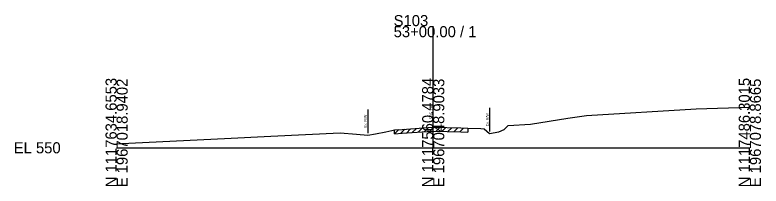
# Model space of a CAD drawing. Extents: x -26 to 163, y -10 to 24018.
# Drawn here: x -25.7 to 162.8, y 2490.3 to 2533.6 of the extents above; entities that cross this region are included whole.
import ezdxf

# ---------------------------------------------------------------- set-up
doc = ezdxf.new("R2010")
doc.units = 0
for name, color, linetype in [('RD_GPK_XS_Cell', 7, 'Continuous'), ('RD_XS_ExGround', 7, 'Continuous'), ('RD_XS_ExPaveRet', 7, 'Continuous'), ('RD_XS_ExRW', 7, 'Continuous'), ('RD_XS_TX_Elev_EX', 7, 'Continuous')]:
    doc.layers.add(name, color=color, linetype=linetype)

msp = doc.modelspace()

# ---------------------------------------------------------------- linework, layer by layer
at = {"layer": 'RD_GPK_XS_Cell'}
for p, q in [((80, 2500), (80, 2530.77)), ((0, 2500), (80, 2500)), ((80, 2500), (160, 2500))]:
    msp.add_line(p, q, dxfattribs=at)
at = {"layer": 'RD_XS_ExGround'}
msp.add_lwpolyline([(0, 2501.04), (1.35, 2501.12), (27.23, 2502.39), (38.97, 2502.95), (56.49, 2503.78), (60.59, 2503.44), (63.45, 2503.22), (65.42, 2503.56), (68.03, 2504.01), (69.5, 2504.37), (70.21, 2504.5), (72.18, 2504.66), (79.7, 2505.2), (80, 2505.19), (86.97, 2505.01), (88.74, 2504.97), (92.04, 2504.86), (92.86, 2504.79), (94.26, 2503.62), (96.57, 2504.06), (97.94, 2504.6), (98.9, 2505.61), (104.54, 2506.01), (113.98, 2507.53), (118.76, 2508.14), (146.41, 2509.86), (160, 2510.26)], dxfattribs=at)
at = {"layer": 'RD_XS_ExPaveRet'}
for p, q in [((70.21, 2503.5), (71.3, 2504.59)), ((70.21, 2503.5), (70.21, 2504.5)), ((71.71, 2503.62), (72.79, 2504.7)), ((72.18, 2503.66), (79.7, 2504.2)), ((73.21, 2503.73), (74.29, 2504.81)), ((74.71, 2503.84), (75.79, 2504.92)), ((76.21, 2503.95), (77.29, 2505.03)), ((77.71, 2504.06), (78.79, 2505.14)), ((79.21, 2504.17), (80.23, 2505.19)), ((79.7, 2504.2), (80, 2504.19)), ((80, 2504.19), (86.97, 2504.01)), ((80.71, 2504.17), (81.69, 2505.15)), ((82.21, 2504.14), (83.19, 2505.11)), ((83.71, 2504.1), (84.69, 2505.07)), ((85.21, 2504.06), (86.19, 2505.03)), ((86.71, 2504.02), (87.69, 2505)), ((86.97, 2504.01), (88.74, 2503.97)), ((88.74, 2504.97), (88.74, 2503.97)), ((70.21, 2503.5), (72.18, 2503.66))]:
    msp.add_line(p, q, dxfattribs=at)
at = {"layer": 'RD_XS_ExRW'}
for p, q in [((63.45, 2509.72), (63.45, 2503.72)), ((94.26, 2510.12), (94.26, 2504.12))]:
    msp.add_line(p, q, dxfattribs=at)

# ---------------------------------------------------------------- texts
at = {"layer": 'RD_GPK_XS_Cell'}
for s, p in [('S103', (70, 2530.77)), ('53+00.00 / 1', (70, 2527.97)), ('EL 550', (-26, 2498.6))]:
    msp.add_text(s, height=2.8, dxfattribs=at).set_placement(p)
for s, p in [('N 1117634.6553', (0, 2490)), ('E 1967018.9402', (2.8, 2490)), ('N 1117560.4784', (80, 2490)), ('E 1967048.9033', (82.8, 2490)), ('N 1117486.3015', (160, 2490)), ('E 1967078.8665', (162.8, 2490))]:
    msp.add_text(s, height=2.8, rotation=90, dxfattribs=at).set_placement(p)
at = {"layer": 'RD_XS_ExRW'}
for p in [(63.2, 2505.07), (94.01, 2505.46)]:
    msp.add_text('Ex. R/W ', height=0.65, rotation=90, dxfattribs=at).set_placement(p)
at = {"layer": 'RD_XS_TX_Elev_EX'}
msp.add_text('555.19', height=0.8, rotation=90, dxfattribs=at).set_placement((79.9, 2507.19))

doc.saveas('drawing.dxf')
